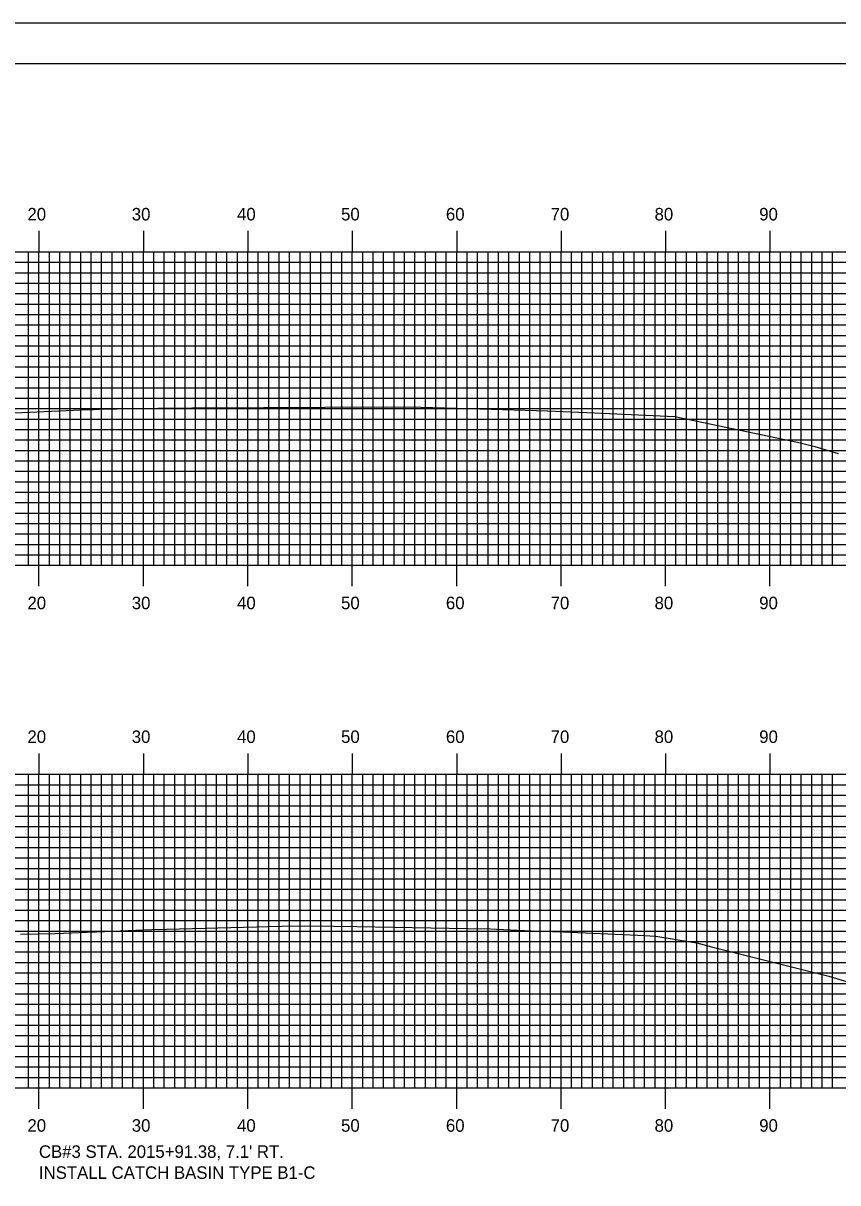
# Model space of a CAD drawing. Extents: x 854681 to 855024, y 366605 to 366825.
# Drawn here: x 854865.1 to 854943.1, y 366714 to 366824.9 of the extents above; entities that cross this region are included whole.
import ezdxf

# ---------------------------------------------------------------- set-up
doc = ezdxf.new("R2010")
doc.units = 0
for name, color, linetype in [('BORDER', 7, 'Continuous'), ('D_Drainage_Text', 7, 'Continuous'), ('H_V ANNOTATION', 7, 'Continuous'), ('M_Roadway_Centerline', 7, 'Continuous'), ('MAJOR', 7, 'Continuous'), ('MINOR', 7, 'Continuous'), ('PLOT BOUNDARY', 7, 'Continuous'), ('S_Roadway_Centerline', 7, 'Continuous')]:
    doc.layers.add(name, color=color, linetype=linetype)

msp = doc.modelspace()

# ---------------------------------------------------------------- linework, layer by layer
at = {"layer": 'BORDER'}
msp.add_lwpolyline([(854696.96, 366611.06), (855016.96, 366611.06), (855016.96, 366821.06), (854696.96, 366821.06)], close=True, dxfattribs=at)
at = {"layer": 'MAJOR'}
for p, q in [((854866.56, 366805.06), (854866.56, 366803.06)), ((854876.56, 366805.06), (854876.56, 366803.06)), ((854886.56, 366805.06), (854886.56, 366803.06)), ((854896.56, 366805.06), (854896.56, 366803.06)), ((854906.56, 366805.06), (854906.56, 366803.06)), ((854916.56, 366805.06), (854916.56, 366803.06)), ((854926.56, 366805.06), (854926.56, 366803.06)), ((854936.56, 366805.06), (854936.56, 366803.06)), ((854706.56, 366803.06), (854986.56, 366803.06)), ((854706.56, 366803.06), (854986.56, 366803.06)), ((854866.56, 366773.06), (854866.56, 366803.06)), ((854876.56, 366773.06), (854876.56, 366803.06)), ((854886.56, 366773.06), (854886.56, 366803.06)), ((854896.56, 366773.06), (854896.56, 366803.06)), ((854906.56, 366773.06), (854906.56, 366803.06)), ((854916.56, 366773.06), (854916.56, 366803.06)), ((854926.56, 366773.06), (854926.56, 366803.06)), ((854936.56, 366773.06), (854936.56, 366803.06)), ((854706.56, 366798.06), (854986.56, 366798.06)), ((854706.56, 366793.06), (854986.56, 366793.06)), ((854706.56, 366788.06), (854986.56, 366788.06)), ((854706.56, 366783.06), (854986.56, 366783.06)), ((854706.56, 366778.06), (854986.56, 366778.06)), ((854706.56, 366773.06), (854986.56, 366773.06)), ((854706.56, 366773.06), (854986.56, 366773.06)), ((854866.56, 366771.05), (854866.56, 366773.06)), ((854876.56, 366771.05), (854876.56, 366773.06)), ((854886.56, 366771.05), (854886.56, 366773.06)), ((854896.56, 366771.05), (854896.56, 366773.06)), ((854906.56, 366771.05), (854906.56, 366773.06)), ((854916.56, 366771.05), (854916.56, 366773.06)), ((854926.56, 366771.05), (854926.56, 366773.06)), ((854936.56, 366771.05), (854936.56, 366773.06)), ((854866.56, 366755.06), (854866.56, 366753.06)), ((854876.56, 366755.06), (854876.56, 366753.06)), ((854886.56, 366755.06), (854886.56, 366753.06)), ((854896.56, 366755.06), (854896.56, 366753.06)), ((854906.56, 366755.06), (854906.56, 366753.06)), ((854916.56, 366755.06), (854916.56, 366753.06)), ((854926.56, 366755.06), (854926.56, 366753.06)), ((854936.56, 366755.06), (854936.56, 366753.06)), ((854706.56, 366753.06), (854986.56, 366753.06)), ((854706.56, 366753.06), (854986.56, 366753.06)), ((854866.56, 366723.06), (854866.56, 366753.06)), ((854876.56, 366723.06), (854876.56, 366753.06)), ((854886.56, 366723.06), (854886.56, 366753.06)), ((854896.56, 366723.06), (854896.56, 366753.06)), ((854906.56, 366723.06), (854906.56, 366753.06)), ((854916.56, 366723.06), (854916.56, 366753.06)), ((854926.56, 366723.06), (854926.56, 366753.06)), ((854936.56, 366723.06), (854936.56, 366753.06)), ((854706.56, 366748.06), (854986.56, 366748.06)), ((854706.56, 366743.06), (854986.56, 366743.06)), ((854706.56, 366738.06), (854986.56, 366738.06)), ((854706.56, 366733.06), (854986.56, 366733.06)), ((854706.56, 366728.06), (854986.56, 366728.06)), ((854706.56, 366723.06), (854986.56, 366723.06)), ((854706.56, 366723.06), (854986.56, 366723.06)), ((854866.56, 366721.05), (854866.56, 366723.06)), ((854876.56, 366721.05), (854876.56, 366723.06)), ((854886.56, 366721.05), (854886.56, 366723.06)), ((854896.56, 366721.05), (854896.56, 366723.06)), ((854906.56, 366721.05), (854906.56, 366723.06)), ((854916.56, 366721.05), (854916.56, 366723.06)), ((854926.56, 366721.05), (854926.56, 366723.06)), ((854936.56, 366721.05), (854936.56, 366723.06))]:
    msp.add_line(p, q, dxfattribs=at)
at = {"layer": 'MINOR'}
for p, q in [((854865.56, 366773.06), (854865.56, 366803.06)), ((854867.56, 366773.06), (854867.56, 366803.06)), ((854868.56, 366773.06), (854868.56, 366803.06)), ((854869.56, 366773.06), (854869.56, 366803.06)), ((854870.56, 366773.06), (854870.56, 366803.06)), ((854871.56, 366773.06), (854871.56, 366803.06)), ((854872.56, 366773.06), (854872.56, 366803.06)), ((854873.56, 366773.06), (854873.56, 366803.06)), ((854874.56, 366773.06), (854874.56, 366803.06)), ((854875.56, 366773.06), (854875.56, 366803.06)), ((854877.56, 366773.06), (854877.56, 366803.06)), ((854878.56, 366773.06), (854878.56, 366803.06)), ((854879.56, 366773.06), (854879.56, 366803.06)), ((854880.56, 366773.06), (854880.56, 366803.06)), ((854881.56, 366773.06), (854881.56, 366803.06)), ((854882.56, 366773.06), (854882.56, 366803.06)), ((854883.56, 366773.06), (854883.56, 366803.06)), ((854884.56, 366773.06), (854884.56, 366803.06)), ((854885.56, 366773.06), (854885.56, 366803.06)), ((854887.56, 366773.06), (854887.56, 366803.06)), ((854888.56, 366773.06), (854888.56, 366803.06)), ((854889.56, 366773.06), (854889.56, 366803.06)), ((854890.56, 366773.06), (854890.56, 366803.06)), ((854891.56, 366773.06), (854891.56, 366803.06)), ((854892.56, 366773.06), (854892.56, 366803.06)), ((854893.56, 366773.06), (854893.56, 366803.06)), ((854894.56, 366773.06), (854894.56, 366803.06)), ((854895.56, 366773.06), (854895.56, 366803.06)), ((854897.56, 366773.06), (854897.56, 366803.06)), ((854898.56, 366773.06), (854898.56, 366803.06)), ((854899.56, 366773.06), (854899.56, 366803.06)), ((854900.56, 366773.06), (854900.56, 366803.06)), ((854901.56, 366773.06), (854901.56, 366803.06)), ((854902.56, 366773.06), (854902.56, 366803.06)), ((854903.56, 366773.06), (854903.56, 366803.06)), ((854904.56, 366773.06), (854904.56, 366803.06)), ((854905.56, 366773.06), (854905.56, 366803.06)), ((854907.56, 366773.06), (854907.56, 366803.06)), ((854908.56, 366773.06), (854908.56, 366803.06)), ((854909.56, 366773.06), (854909.56, 366803.06)), ((854910.56, 366773.06), (854910.56, 366803.06)), ((854911.56, 366773.06), (854911.56, 366803.06)), ((854912.56, 366773.06), (854912.56, 366803.06)), ((854913.56, 366773.06), (854913.56, 366803.06)), ((854914.56, 366773.06), (854914.56, 366803.06)), ((854915.56, 366773.06), (854915.56, 366803.06)), ((854917.56, 366773.06), (854917.56, 366803.06)), ((854918.56, 366773.06), (854918.56, 366803.06)), ((854919.56, 366773.06), (854919.56, 366803.06)), ((854920.56, 366773.06), (854920.56, 366803.06)), ((854921.56, 366773.06), (854921.56, 366803.06)), ((854922.56, 366773.06), (854922.56, 366803.06)), ((854923.56, 366773.06), (854923.56, 366803.06)), ((854924.56, 366773.06), (854924.56, 366803.06)), ((854925.56, 366773.06), (854925.56, 366803.06)), ((854927.56, 366773.06), (854927.56, 366803.06)), ((854928.56, 366773.06), (854928.56, 366803.06)), ((854929.56, 366773.06), (854929.56, 366803.06)), ((854930.56, 366773.06), (854930.56, 366803.06)), ((854931.56, 366773.06), (854931.56, 366803.06)), ((854932.56, 366773.06), (854932.56, 366803.06)), ((854933.56, 366773.06), (854933.56, 366803.06)), ((854934.56, 366773.06), (854934.56, 366803.06)), ((854935.56, 366773.06), (854935.56, 366803.06)), ((854937.56, 366773.06), (854937.56, 366803.06)), ((854938.56, 366773.06), (854938.56, 366803.06)), ((854939.56, 366773.06), (854939.56, 366803.06)), ((854940.56, 366773.06), (854940.56, 366803.06)), ((854941.56, 366773.06), (854941.56, 366803.06)), ((854942.56, 366773.06), (854942.56, 366803.06)), ((854706.56, 366802.06), (854986.56, 366802.06)), ((854706.56, 366801.06), (854986.56, 366801.06)), ((854706.56, 366800.06), (854986.56, 366800.06)), ((854706.56, 366799.06), (854986.56, 366799.06)), ((854706.56, 366797.06), (854986.56, 366797.06)), ((854706.56, 366796.06), (854986.56, 366796.06)), ((854706.56, 366795.06), (854986.56, 366795.06)), ((854706.56, 366794.06), (854986.56, 366794.06)), ((854706.56, 366792.06), (854986.56, 366792.06)), ((854706.56, 366791.06), (854986.56, 366791.06)), ((854706.56, 366790.06), (854986.56, 366790.06)), ((854706.56, 366789.06), (854986.56, 366789.06)), ((854706.56, 366787.06), (854986.56, 366787.06)), ((854706.56, 366786.06), (854986.56, 366786.06)), ((854706.56, 366785.06), (854986.56, 366785.06)), ((854706.56, 366784.06), (854986.56, 366784.06)), ((854706.56, 366782.06), (854986.56, 366782.06)), ((854706.56, 366781.06), (854986.56, 366781.06)), ((854706.56, 366780.06), (854986.56, 366780.06)), ((854706.56, 366779.06), (854986.56, 366779.06)), ((854706.56, 366777.06), (854986.56, 366777.06)), ((854706.56, 366776.06), (854986.56, 366776.06)), ((854706.56, 366775.06), (854986.56, 366775.06)), ((854706.56, 366774.06), (854986.56, 366774.06)), ((854865.56, 366723.06), (854865.56, 366753.06)), ((854867.56, 366723.06), (854867.56, 366753.06)), ((854868.56, 366723.06), (854868.56, 366753.06)), ((854869.56, 366723.06), (854869.56, 366753.06)), ((854870.56, 366723.06), (854870.56, 366753.06)), ((854871.56, 366723.06), (854871.56, 366753.06)), ((854872.56, 366723.06), (854872.56, 366753.06)), ((854873.56, 366723.06), (854873.56, 366753.06)), ((854874.56, 366723.06), (854874.56, 366753.06)), ((854875.56, 366723.06), (854875.56, 366753.06)), ((854877.56, 366723.06), (854877.56, 366753.06)), ((854878.56, 366723.06), (854878.56, 366753.06)), ((854879.56, 366723.06), (854879.56, 366753.06)), ((854880.56, 366723.06), (854880.56, 366753.06)), ((854881.56, 366723.06), (854881.56, 366753.06)), ((854882.56, 366723.06), (854882.56, 366753.06)), ((854883.56, 366723.06), (854883.56, 366753.06)), ((854884.56, 366723.06), (854884.56, 366753.06)), ((854885.56, 366723.06), (854885.56, 366753.06)), ((854887.56, 366723.06), (854887.56, 366753.06)), ((854888.56, 366723.06), (854888.56, 366753.06)), ((854889.56, 366723.06), (854889.56, 366753.06)), ((854890.56, 366723.06), (854890.56, 366753.06)), ((854891.56, 366723.06), (854891.56, 366753.06)), ((854892.56, 366723.06), (854892.56, 366753.06)), ((854893.56, 366723.06), (854893.56, 366753.06)), ((854894.56, 366723.06), (854894.56, 366753.06)), ((854895.56, 366723.06), (854895.56, 366753.06)), ((854897.56, 366723.06), (854897.56, 366753.06)), ((854898.56, 366723.06), (854898.56, 366753.06)), ((854899.56, 366723.06), (854899.56, 366753.06)), ((854900.56, 366723.06), (854900.56, 366753.06)), ((854901.56, 366723.06), (854901.56, 366753.06)), ((854902.56, 366723.06), (854902.56, 366753.06)), ((854903.56, 366723.06), (854903.56, 366753.06)), ((854904.56, 366723.06), (854904.56, 366753.06)), ((854905.56, 366723.06), (854905.56, 366753.06)), ((854907.56, 366723.06), (854907.56, 366753.06)), ((854908.56, 366723.06), (854908.56, 366753.06)), ((854909.56, 366723.06), (854909.56, 366753.06)), ((854910.56, 366723.06), (854910.56, 366753.06)), ((854911.56, 366723.06), (854911.56, 366753.06)), ((854912.56, 366723.06), (854912.56, 366753.06)), ((854913.56, 366723.06), (854913.56, 366753.06)), ((854914.56, 366723.06), (854914.56, 366753.06)), ((854915.56, 366723.06), (854915.56, 366753.06)), ((854917.56, 366723.06), (854917.56, 366753.06)), ((854918.56, 366723.06), (854918.56, 366753.06)), ((854919.56, 366723.06), (854919.56, 366753.06)), ((854920.56, 366723.06), (854920.56, 366753.06)), ((854921.56, 366723.06), (854921.56, 366753.06)), ((854922.56, 366723.06), (854922.56, 366753.06)), ((854923.56, 366723.06), (854923.56, 366753.06)), ((854924.56, 366723.06), (854924.56, 366753.06)), ((854925.56, 366723.06), (854925.56, 366753.06)), ((854927.56, 366723.06), (854927.56, 366753.06)), ((854928.56, 366723.06), (854928.56, 366753.06)), ((854929.56, 366723.06), (854929.56, 366753.06)), ((854930.56, 366723.06), (854930.56, 366753.06)), ((854931.56, 366723.06), (854931.56, 366753.06)), ((854932.56, 366723.06), (854932.56, 366753.06)), ((854933.56, 366723.06), (854933.56, 366753.06)), ((854934.56, 366723.06), (854934.56, 366753.06)), ((854935.56, 366723.06), (854935.56, 366753.06)), ((854937.56, 366723.06), (854937.56, 366753.06)), ((854938.56, 366723.06), (854938.56, 366753.06)), ((854939.56, 366723.06), (854939.56, 366753.06)), ((854940.56, 366723.06), (854940.56, 366753.06)), ((854941.56, 366723.06), (854941.56, 366753.06)), ((854942.56, 366723.06), (854942.56, 366753.06)), ((854706.56, 366752.06), (854986.56, 366752.06)), ((854706.56, 366751.06), (854986.56, 366751.06)), ((854706.56, 366750.06), (854986.56, 366750.06)), ((854706.56, 366749.06), (854986.56, 366749.06)), ((854706.56, 366747.06), (854986.56, 366747.06)), ((854706.56, 366746.06), (854986.56, 366746.06)), ((854706.56, 366745.06), (854986.56, 366745.06)), ((854706.56, 366744.06), (854986.56, 366744.06)), ((854706.56, 366742.06), (854986.56, 366742.06)), ((854706.56, 366741.06), (854986.56, 366741.06)), ((854706.56, 366740.06), (854986.56, 366740.06)), ((854706.56, 366739.06), (854986.56, 366739.06)), ((854706.56, 366737.06), (854986.56, 366737.06)), ((854706.56, 366736.06), (854986.56, 366736.06)), ((854706.56, 366735.06), (854986.56, 366735.06)), ((854706.56, 366734.06), (854986.56, 366734.06)), ((854706.56, 366732.06), (854986.56, 366732.06)), ((854706.56, 366731.06), (854986.56, 366731.06)), ((854706.56, 366730.06), (854986.56, 366730.06)), ((854706.56, 366729.06), (854986.56, 366729.06)), ((854706.56, 366727.06), (854986.56, 366727.06)), ((854706.56, 366726.06), (854986.56, 366726.06)), ((854706.56, 366725.06), (854986.56, 366725.06)), ((854706.56, 366724.06), (854986.56, 366724.06))]:
    msp.add_line(p, q, dxfattribs=at)
at = {"layer": 'PLOT BOUNDARY'}
msp.add_lwpolyline([(854680.77, 366604.94), (855020.77, 366604.94), (855020.77, 366824.94), (854680.77, 366824.94)], close=True, dxfattribs=at)
at = {"layer": 'S_Roadway_Centerline'}
for points in [[(854859.27, 366787.44), (854871.29, 366787.96), (854871.86, 366787.98), (854871.98, 366787.99), (854872, 366787.99), (854872.35, 366787.99), (854874.01, 366788.02), (854877.93, 366788.09), (854881.19, 366788.14), (854888.05, 366788.16), (854899.8, 366788.24), (854903.12, 366788.19), (854909.91, 366788), (854910.95, 366787.96), (854915.26, 366787.84), (854919.02, 366787.68), (854921.2, 366787.6), (854927.44, 366787.3), (854939.19, 366784.86), (854940.85, 366784.44), (854943.09, 366783.76)], [(854864.78, 366737.76), (854868.15, 366737.84), (854871.96, 366737.99), (854872.08, 366738), (854876.62, 366738.18), (854877.37, 366738.21), (854878.76, 366738.24), (854889.84, 366738.53), (854892.57, 366738.57), (854897.01, 366738.49), (854907.62, 366738.3), (854909.79, 366738.27), (854910.38, 366738.24), (854913.74, 366738.1), (854916.71, 366737.98), (854923.91, 366737.67), (854925.63, 366737.58), (854929.15, 366737), (854929.55, 366736.93), (854930.97, 366736.54), (854942.2, 366733.74), (854947.74, 366732.06)]]:
    msp.add_lwpolyline(points, dxfattribs=at)

# ---------------------------------------------------------------- texts
at = {"layer": 'D_Drainage_Text'}
for s, p in [("CB#3 STA. 2015+91.38, 7.1' RT.", (854866.56, 366716.36)), ('INSTALL CATCH BASIN TYPE B1-C', (854866.56, 366714.35))]:
    msp.add_text(s, height=1.2, dxfattribs=at).set_placement(p)
at = {"layer": 'H_V ANNOTATION'}
for s, p in [('20', (854865.46, 366806.06)), ('30', (854875.45, 366806.06)), ('40', (854885.53, 366806.06)), ('50', (854895.49, 366806.06)), ('60', (854905.53, 366806.06)), ('70', (854915.56, 366806.06)), ('80', (854925.51, 366806.06)), ('90', (854935.53, 366806.06)), ('20', (854865.46, 366768.86)), ('30', (854875.45, 366768.86)), ('40', (854885.53, 366768.86)), ('50', (854895.49, 366768.86)), ('60', (854905.53, 366768.86)), ('70', (854915.56, 366768.86)), ('80', (854925.51, 366768.86)), ('90', (854935.53, 366768.86)), ('20', (854865.46, 366756.06)), ('30', (854875.45, 366756.06)), ('40', (854885.53, 366756.06)), ('50', (854895.49, 366756.06)), ('60', (854905.53, 366756.06)), ('70', (854915.56, 366756.06)), ('80', (854925.51, 366756.06)), ('90', (854935.53, 366756.06)), ('20', (854865.46, 366718.86)), ('30', (854875.45, 366718.86)), ('40', (854885.53, 366718.86)), ('50', (854895.49, 366718.86)), ('60', (854905.53, 366718.86)), ('70', (854915.56, 366718.86)), ('80', (854925.51, 366718.86)), ('90', (854935.53, 366718.86))]:
    msp.add_text(s, height=1.2, dxfattribs=at).set_placement(p)
at = {"layer": 'M_Roadway_Centerline'}
for s, p in [('C', (854871.97, 366787.99)), ('L', (854871.98, 366787.98)), ('C', (854910.95, 366787.96)), ('L', (854910.95, 366787.95)), ('C', (854877.37, 366738.21)), ('L', (854877.37, 366738.21)), ('C', (854909.79, 366738.27)), ('L', (854909.79, 366738.26))]:
    msp.add_text(s, height=0.0146, dxfattribs=at).set_placement(p)

doc.saveas('drawing.dxf')
